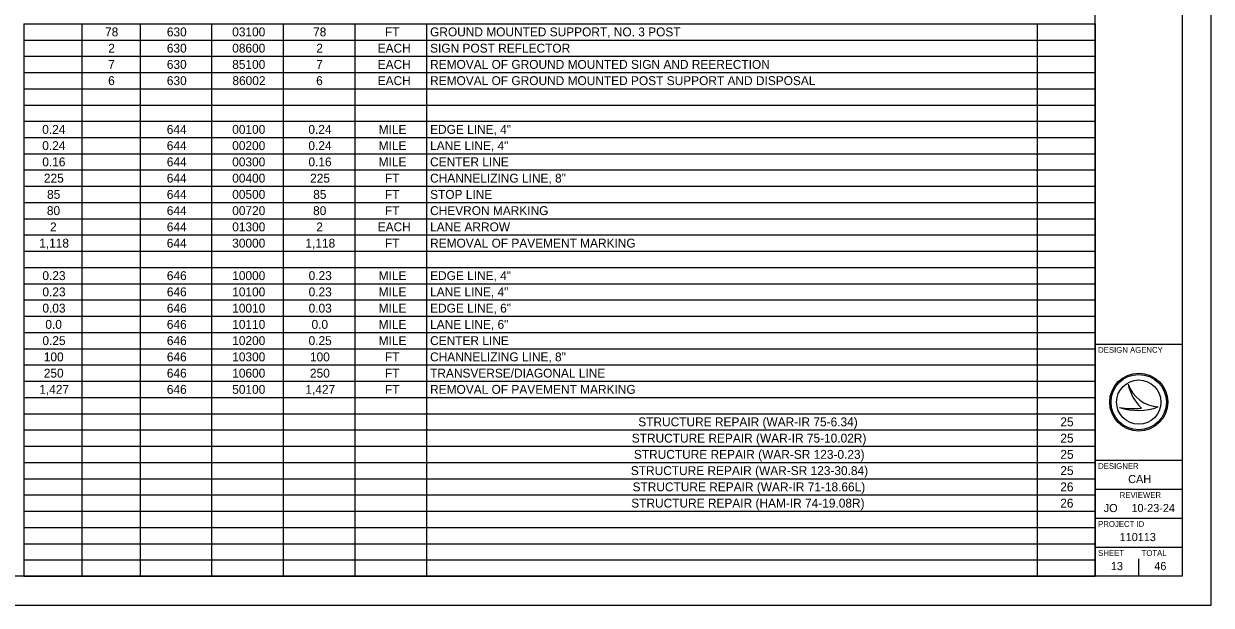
# Model space of a CAD drawing. Extents: x 0 to 34, y 0 to 22.
# Drawn here: x 13.53 to 34, y 0 to 10.02 of the extents above; entities that cross this region are included whole.
import ezdxf

# ---------------------------------------------------------------- set-up
doc = ezdxf.new("R2010")
doc.units = 0
for name, color, linetype in [('SH_Border', 7, 'Continuous'), ('SH_Cut_Line', 7, 'Continuous'), ('SH_Data', 7, 'Continuous'), ('SH_Text', 7, 'Continuous')]:
    doc.layers.add(name, color=color, linetype=linetype)

msp = doc.modelspace()

# ---------------------------------------------------------------- linework, layer by layer
at = {"layer": 'SH_Border'}
for p, q in [((32, 0.5), (32, 21.5)), ((32, 4.5), (33.5, 4.5)), ((32, 2.5), (33.5, 2.5)), ((32, 2), (33.5, 2)), ((32, 1.5), (33.5, 1.5)), ((32, 1), (33.5, 1))]:
    msp.add_line(p, q, dxfattribs=at)
msp.add_lwpolyline([(1.5, 21.5), (33.5, 21.5), (33.5, 0.5), (1.5, 0.5)], close=True, dxfattribs=at)
at = {"layer": 'SH_Cut_Line'}
msp.add_lwpolyline([(0, 0), (34, 0), (34, 22), (0, 22)], close=True, dxfattribs=at)
at = {"layer": 'SH_Data'}
for p, q in [((32.567, 3.81), (32.567, 3.81)), ((32.75, 3.5), (32.75, 3.5)), ((32.417, 3.41), (32.417, 3.41)), ((33.087, 3.419), (33.087, 3.419)), ((32.375, 0.675), (32.375, 0.675)), ((32.75, 0.5), (32.75, 0.8))]:
    msp.add_line(p, q, dxfattribs=at)
for radius in [0.5, 0.477, 0.477, 0.382]:
    msp.add_circle((32.75, 3.5), radius, dxfattribs=at)
for centre, radius, start, end in [((33.116, 3.998), 0.58, 198.9257, 198.9319), ((33.347, 3.97), 0.796, 191.6379, 191.6421), ((33.116, 3.998), 0.58, 198.9319, 267.1657), ((33.347, 3.97), 0.796, 191.6421, 226.0947), ((32.739, 4.37), 1.013, 251.4576, 290.0832), ((32.648, 4.654), 1.266, 259.4964, 259.4995), ((32.739, 4.37), 1.013, 251.4527, 251.4576), ((32.648, 4.654), 1.266, 259.4995, 276.6672)]:
    msp.add_arc(centre, radius, start, end, dxfattribs=at)
at = {"layer": 'SH_Text'}
for p, q in [((13.53, 10.02), (15.535, 10.02)), ((13.53, 10.02), (13.53, 9.74)), ((14.533, 10.02), (14.533, 9.74)), ((15.535, 10.02), (32, 10.02)), ((15.535, 10.02), (15.535, 9.74)), ((16.769, 10.02), (16.769, 9.74)), ((18.003, 10.02), (18.003, 9.74)), ((19.237, 10.02), (19.237, 9.74)), ((20.471, 10.02), (20.471, 9.74)), ((30.997, 10.02), (30.997, 9.74)), ((32, 10.02), (32, 9.74)), ((13.53, 9.74), (15.535, 9.74)), ((13.53, 9.74), (13.53, 8.9)), ((14.533, 9.74), (14.533, 8.9)), ((15.535, 9.74), (32, 9.74)), ((15.535, 9.74), (15.535, 8.9)), ((16.769, 9.74), (16.769, 8.9)), ((18.003, 9.74), (18.003, 8.9)), ((19.237, 9.74), (19.237, 8.9)), ((20.471, 9.74), (20.471, 8.9)), ((30.997, 9.74), (30.997, 8.9)), ((32, 9.74), (32, 8.9)), ((13.53, 9.46), (15.535, 9.46)), ((15.535, 9.46), (32, 9.46)), ((13.53, 9.18), (15.535, 9.18)), ((15.535, 9.18), (32, 9.18)), ((13.53, 8.9), (15.535, 8.9)), ((13.53, 8.9), (13.53, 8.34)), ((14.533, 8.9), (14.533, 8.34)), ((15.535, 8.9), (32, 8.9)), ((15.535, 8.9), (15.535, 8.34)), ((16.769, 8.9), (16.769, 8.34)), ((18.003, 8.9), (18.003, 8.34)), ((19.237, 8.9), (19.237, 8.34)), ((20.471, 8.9), (20.471, 8.34)), ((30.997, 8.9), (30.997, 8.34)), ((32, 8.9), (32, 8.34)), ((13.53, 8.62), (15.535, 8.62)), ((15.535, 8.62), (32, 8.62)), ((13.53, 8.34), (15.535, 8.34)), ((13.53, 8.34), (13.53, 7.5)), ((14.533, 8.34), (14.533, 7.5)), ((15.535, 8.34), (32, 8.34)), ((15.535, 8.34), (15.535, 7.5)), ((16.769, 8.34), (16.769, 7.5)), ((18.003, 8.34), (18.003, 7.5)), ((19.237, 8.34), (19.237, 7.5)), ((20.471, 8.34), (20.471, 7.5)), ((30.997, 8.34), (30.997, 7.5)), ((32, 8.34), (32, 7.5)), ((13.53, 8.06), (15.535, 8.06)), ((15.535, 8.06), (32, 8.06)), ((13.53, 7.78), (15.535, 7.78)), ((15.535, 7.78), (32, 7.78)), ((13.53, 7.5), (15.535, 7.5)), ((13.53, 7.5), (13.53, 6.94)), ((14.533, 7.5), (14.533, 6.94)), ((15.535, 7.5), (32, 7.5)), ((15.535, 7.5), (15.535, 6.94)), ((16.769, 7.5), (16.769, 6.94)), ((18.003, 7.5), (18.003, 6.94)), ((19.237, 7.5), (19.237, 6.94)), ((20.471, 7.5), (20.471, 6.94)), ((30.997, 7.5), (30.997, 6.94)), ((32, 7.5), (32, 6.94)), ((13.53, 7.22), (15.535, 7.22)), ((15.535, 7.22), (32, 7.22)), ((13.53, 6.94), (15.535, 6.94)), ((13.53, 6.94), (13.53, 6.1)), ((14.533, 6.94), (14.533, 6.1)), ((15.535, 6.94), (32, 6.94)), ((15.535, 6.94), (15.535, 6.1)), ((16.769, 6.94), (16.769, 6.1)), ((18.003, 6.94), (18.003, 6.1)), ((19.237, 6.94), (19.237, 6.1)), ((20.471, 6.94), (20.471, 6.1)), ((30.997, 6.94), (30.997, 6.1)), ((32, 6.94), (32, 6.1)), ((13.53, 6.66), (15.535, 6.66)), ((15.535, 6.66), (32, 6.66)), ((13.53, 6.38), (15.535, 6.38)), ((15.535, 6.38), (32, 6.38)), ((13.53, 6.1), (15.535, 6.1)), ((13.53, 6.1), (13.53, 4.98)), ((14.533, 6.1), (14.533, 4.98)), ((15.535, 6.1), (32, 6.1)), ((15.535, 6.1), (15.535, 4.98)), ((16.769, 6.1), (16.769, 4.98)), ((18.003, 6.1), (18.003, 4.98)), ((19.237, 6.1), (19.237, 4.98)), ((20.471, 6.1), (20.471, 4.98)), ((30.997, 6.1), (30.997, 4.98)), ((32, 6.1), (32, 4.98)), ((13.53, 5.82), (15.535, 5.82)), ((15.535, 5.82), (32, 5.82)), ((13.53, 5.54), (15.535, 5.54)), ((15.535, 5.54), (32, 5.54)), ((13.53, 5.26), (15.535, 5.26)), ((15.535, 5.26), (32, 5.26)), ((13.53, 4.98), (15.535, 4.98)), ((13.53, 4.98), (13.53, 4.7)), ((14.533, 4.98), (14.533, 4.7)), ((15.535, 4.98), (32, 4.98)), ((15.535, 4.98), (15.535, 4.7)), ((16.769, 4.98), (16.769, 4.7)), ((18.003, 4.98), (18.003, 4.7)), ((19.237, 4.98), (19.237, 4.7)), ((20.471, 4.98), (20.471, 4.7)), ((30.997, 4.98), (30.997, 4.7)), ((32, 4.98), (32, 4.7)), ((13.53, 4.7), (15.535, 4.7)), ((13.53, 4.7), (13.53, 3.58)), ((14.533, 4.7), (14.533, 3.58)), ((15.535, 4.7), (32, 4.7)), ((15.535, 4.7), (15.535, 3.58)), ((16.769, 4.7), (16.769, 3.58)), ((18.003, 4.7), (18.003, 3.58)), ((19.237, 4.7), (19.237, 3.58)), ((20.471, 4.7), (20.471, 3.58)), ((30.997, 4.7), (30.997, 3.58)), ((32, 4.7), (32, 3.58)), ((13.53, 4.42), (15.535, 4.42)), ((15.535, 4.42), (32, 4.42)), ((13.53, 4.14), (15.535, 4.14)), ((15.535, 4.14), (32, 4.14)), ((13.53, 3.86), (15.535, 3.86)), ((15.535, 3.86), (32, 3.86)), ((13.53, 3.58), (15.535, 3.58)), ((13.53, 3.58), (13.53, 3.3)), ((14.533, 3.58), (14.533, 3.3)), ((15.535, 3.58), (32, 3.58)), ((15.535, 3.58), (15.535, 3.3)), ((16.769, 3.58), (16.769, 3.3)), ((18.003, 3.58), (18.003, 3.3)), ((19.237, 3.58), (19.237, 3.3)), ((20.471, 3.58), (20.471, 3.3)), ((30.997, 3.58), (30.997, 3.3)), ((32, 3.58), (32, 3.3)), ((13.53, 3.3), (15.535, 3.3)), ((13.53, 3.3), (13.53, 2.18)), ((14.533, 3.3), (14.533, 2.18)), ((15.535, 3.3), (32, 3.3)), ((15.535, 3.3), (15.535, 2.18)), ((16.769, 3.3), (16.769, 2.18)), ((18.003, 3.3), (18.003, 2.18)), ((19.237, 3.3), (19.237, 2.18)), ((20.471, 3.3), (20.471, 2.18)), ((30.997, 3.3), (30.997, 2.18)), ((32, 3.3), (32, 2.18)), ((13.53, 3.02), (15.535, 3.02)), ((15.535, 3.02), (32, 3.02)), ((13.53, 2.74), (15.535, 2.74)), ((15.535, 2.74), (32, 2.74)), ((13.53, 2.46), (15.535, 2.46)), ((15.535, 2.46), (32, 2.46)), ((13.53, 2.18), (15.535, 2.18)), ((13.53, 2.18), (13.53, 1.9)), ((14.533, 2.18), (14.533, 1.9)), ((15.535, 2.18), (32, 2.18)), ((15.535, 2.18), (15.535, 1.9)), ((16.769, 2.18), (16.769, 1.9)), ((18.003, 2.18), (18.003, 1.9)), ((19.237, 2.18), (19.237, 1.9)), ((20.471, 2.18), (20.471, 1.9)), ((30.997, 2.18), (30.997, 1.9)), ((32, 2.18), (32, 1.9)), ((13.53, 1.9), (15.535, 1.9)), ((13.53, 1.9), (13.53, 0.78)), ((14.533, 1.9), (14.533, 0.78)), ((15.535, 1.9), (32, 1.9)), ((15.535, 1.9), (15.535, 0.78)), ((16.769, 1.9), (16.769, 0.78)), ((18.003, 1.9), (18.003, 0.78)), ((19.237, 1.9), (19.237, 0.78)), ((20.471, 1.9), (20.471, 0.78)), ((30.997, 1.9), (30.997, 0.78)), ((32, 1.9), (32, 0.78)), ((13.53, 1.62), (15.535, 1.62)), ((15.535, 1.62), (32, 1.62)), ((13.53, 1.34), (15.535, 1.34)), ((15.535, 1.34), (32, 1.34)), ((13.53, 1.06), (15.535, 1.06)), ((15.535, 1.06), (32, 1.06)), ((13.53, 0.78), (15.535, 0.78)), ((13.53, 0.78), (13.53, 0.5)), ((14.533, 0.78), (14.533, 0.5)), ((15.535, 0.78), (32, 0.78)), ((15.535, 0.78), (15.535, 0.5)), ((16.769, 0.78), (16.769, 0.5)), ((18.003, 0.78), (18.003, 0.5)), ((19.237, 0.78), (19.237, 0.5)), ((20.471, 0.78), (20.471, 0.5)), ((30.997, 0.78), (30.997, 0.5)), ((32, 0.78), (32, 0.5)), ((13.53, 0.5), (15.535, 0.5)), ((15.535, 0.5), (32, 0.5))]:
    msp.add_line(p, q, dxfattribs=at)

# ---------------------------------------------------------------- texts
at = {"layer": 'SH_Data'}
for s, height, p in [('DESIGN AGENCY', 0.1, (32.05, 4.35)), ('DESIGNER', 0.1, (32.05, 2.35)), ('CAH', 0.14, (32.568, 2.105)), ('REVIEWER', 0.1, (32.422, 1.85)), ('JO', 0.14, (32.147, 1.605)), ('10-23-24', 0.14, (32.625, 1.605)), ('PROJECT ID', 0.1, (32.05, 1.35)), ('110113', 0.14, (32.421, 1.105)), ('SHEET', 0.1, (32.05, 0.85)), ('TOTAL', 0.1, (32.8, 0.85)), ('13', 0.14, (32.27, 0.605)), ('46', 0.14, (33.018, 0.605))]:
    msp.add_text(s, height=height, dxfattribs=at).set_placement(p)
at = {"layer": 'SH_Text'}
for s, height, p in [('78', 0.1533, (14.932, 9.803)), ('630', 0.1533, (15.997, 9.803)), ('03100', 0.1533, (17.124, 9.803)), ('78', 0.1533, (18.518, 9.803)), ('FT', 0.1533, (19.756, 9.803)), ('GROUND MOUNTED SUPPORT, NO. 3 POST', 0.15333, (20.535, 9.803)), ('2', 0.153, (14.987, 9.523)), ('630', 0.1533, (15.997, 9.523)), ('08600', 0.1533, (17.124, 9.523)), ('2', 0.153, (18.573, 9.523)), ('EACH', 0.1533, (19.632, 9.523)), ('SIGN POST REFLECTOR', 0.15333, (20.535, 9.523)), ('7', 0.153, (14.986, 9.243)), ('630', 0.1533, (15.997, 9.243)), ('85100', 0.1533, (17.124, 9.243)), ('7', 0.153, (18.572, 9.243)), ('EACH', 0.1533, (19.632, 9.243)), ('REMOVAL OF GROUND MOUNTED SIGN AND REERECTION', 0.15333, (20.535, 9.243)), ('6', 0.153, (14.985, 8.963)), ('630', 0.1533, (15.997, 8.963)), ('86002', 0.1533, (17.127, 8.963)), ('6', 0.153, (18.571, 8.963)), ('EACH', 0.1533, (19.632, 8.963)), ('REMOVAL OF GROUND MOUNTED POST SUPPORT AND DISPOSAL', 0.15333, (20.535, 8.963)), ('0.24', 0.1533, (13.849, 8.123)), ('644', 0.1533, (15.996, 8.123)), ('00100', 0.1533, (17.124, 8.123)), ('0.24', 0.1533, (18.437, 8.123)), ('MILE', 0.1533, (19.648, 8.123)), ('EDGE LINE, 4"', 0.15333, (20.535, 8.123)), ('0.24', 0.1533, (13.849, 7.843)), ('644', 0.1533, (15.996, 7.843)), ('00200', 0.1533, (17.124, 7.843)), ('0.24', 0.1533, (18.437, 7.843)), ('MILE', 0.1533, (19.648, 7.843)), ('LANE LINE, 4"', 0.15333, (20.535, 7.843)), ('0.16', 0.1533, (13.85, 7.563)), ('644', 0.1533, (15.996, 7.563)), ('00300', 0.1533, (17.124, 7.563)), ('0.16', 0.1533, (18.438, 7.563)), ('MILE', 0.1533, (19.648, 7.563)), ('CENTER LINE', 0.15333, (20.535, 7.563)), ('225', 0.1533, (13.878, 7.283)), ('644', 0.1533, (15.996, 7.283)), ('00400', 0.1533, (17.124, 7.283)), ('225', 0.1533, (18.467, 7.283)), ('FT', 0.1533, (19.756, 7.283)), ('CHANNELIZING LINE, 8"', 0.15333, (20.535, 7.283)), ('85', 0.1533, (13.932, 7.003)), ('644', 0.1533, (15.996, 7.003)), ('00500', 0.1533, (17.124, 7.003)), ('85', 0.1533, (18.52, 7.003)), ('FT', 0.1533, (19.756, 7.003)), ('STOP LINE', 0.1533, (20.535, 7.003)), ('80', 0.1533, (13.929, 6.723)), ('644', 0.1533, (15.996, 6.723)), ('00720', 0.1533, (17.124, 6.723)), ('80', 0.1533, (18.518, 6.723)), ('FT', 0.1533, (19.756, 6.723)), ('CHEVRON MARKING', 0.15333, (20.535, 6.723)), ('2', 0.153, (13.984, 6.443)), ('644', 0.1533, (15.996, 6.443)), ('01300', 0.1533, (17.124, 6.443)), ('2', 0.153, (18.573, 6.443)), ('EACH', 0.1533, (19.632, 6.443)), ('LANE ARROW', 0.1533, (20.535, 6.443)), ('1,118', 0.1533, (13.797, 6.163)), ('644', 0.1533, (15.996, 6.163)), ('30000', 0.1533, (17.124, 6.163)), ('1,118', 0.1533, (18.386, 6.163)), ('FT', 0.1533, (19.756, 6.163)), ('REMOVAL OF PAVEMENT MARKING', 0.15333, (20.535, 6.163)), ('0.23', 0.1533, (13.852, 5.603)), ('646', 0.1533, (15.997, 5.603)), ('10000', 0.1533, (17.124, 5.603)), ('0.23', 0.1533, (18.441, 5.603)), ('MILE', 0.1533, (19.648, 5.603)), ('EDGE LINE, 4"', 0.15333, (20.535, 5.603)), ('0.23', 0.1533, (13.852, 5.323)), ('646', 0.1533, (15.997, 5.323)), ('10100', 0.1533, (17.124, 5.323)), ('0.23', 0.1533, (18.441, 5.323)), ('MILE', 0.1533, (19.648, 5.323)), ('LANE LINE, 4"', 0.15333, (20.535, 5.323)), ('0.03', 0.1533, (13.852, 5.043)), ('646', 0.1533, (15.997, 5.043)), ('10010', 0.1533, (17.124, 5.043)), ('0.03', 0.1533, (18.441, 5.043)), ('MILE', 0.1533, (19.648, 5.043)), ('EDGE LINE, 6"', 0.15333, (20.535, 5.043)), ('0.0', 0.1533, (13.903, 4.763)), ('646', 0.1533, (15.997, 4.763)), ('10110', 0.1533, (17.124, 4.763)), ('0.0', 0.1533, (18.491, 4.763)), ('MILE', 0.1533, (19.648, 4.763)), ('LANE LINE, 6"', 0.15333, (20.535, 4.763)), ('0.25', 0.1533, (13.852, 4.483)), ('646', 0.1533, (15.997, 4.483)), ('10200', 0.1533, (17.124, 4.483)), ('0.25', 0.1533, (18.44, 4.483)), ('MILE', 0.1533, (19.648, 4.483)), ('CENTER LINE', 0.15333, (20.535, 4.483)), ('100', 0.1533, (13.876, 4.203)), ('646', 0.1533, (15.997, 4.203)), ('10300', 0.1533, (17.124, 4.203)), ('100', 0.1533, (18.464, 4.203)), ('FT', 0.1533, (19.756, 4.203)), ('CHANNELIZING LINE, 8"', 0.15333, (20.535, 4.203)), ('250', 0.1533, (13.876, 3.923)), ('646', 0.1533, (15.997, 3.923)), ('10600', 0.1533, (17.124, 3.923)), ('250', 0.1533, (18.464, 3.923)), ('FT', 0.1533, (19.756, 3.923)), ('TRANSVERSE/DIAGONAL LINE', 0.15333, (20.535, 3.923)), ('1,427', 0.1533, (13.798, 3.643)), ('646', 0.1533, (15.997, 3.643)), ('50100', 0.1533, (17.124, 3.643)), ('1,427', 0.1533, (18.386, 3.643)), ('FT', 0.1533, (19.756, 3.643)), ('REMOVAL OF PAVEMENT MARKING', 0.15333, (20.535, 3.643)), ('STRUCTURE REPAIR (WAR-IR 75-6.34)', 0.15333, (24.123, 3.083)), ('25', 0.1533, (31.399, 3.083)), ('STRUCTURE REPAIR (WAR-IR 75-10.02R)', 0.15333, (24.011, 2.803)), ('25', 0.1533, (31.399, 2.803)), ('STRUCTURE REPAIR (WAR-SR 123-0.23)', 0.15333, (24.048, 2.523)), ('25', 0.1533, (31.399, 2.523)), ('STRUCTURE REPAIR (WAR-SR 123-30.84)', 0.15333, (23.995, 2.243)), ('25', 0.1533, (31.399, 2.243)), ('STRUCTURE REPAIR (WAR-IR 71-18.66L)', 0.15333, (24.025, 1.963)), ('26', 0.1533, (31.397, 1.963)), ('STRUCTURE REPAIR (HAM-IR 74-19.08R)', 0.15333, (24.002, 1.683)), ('26', 0.1533, (31.397, 1.683))]:
    msp.add_text(s, height=height, dxfattribs=at).set_placement(p)

doc.saveas('drawing.dxf')
